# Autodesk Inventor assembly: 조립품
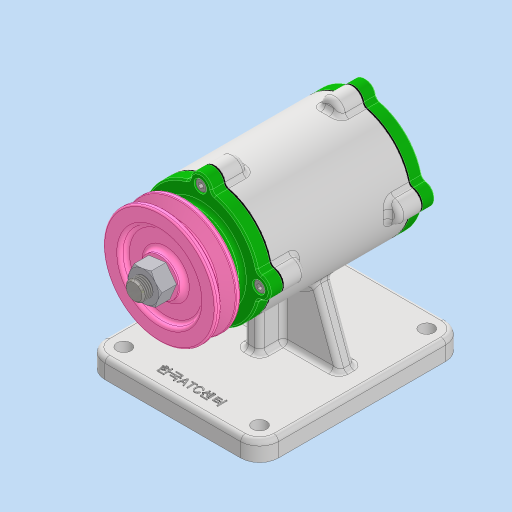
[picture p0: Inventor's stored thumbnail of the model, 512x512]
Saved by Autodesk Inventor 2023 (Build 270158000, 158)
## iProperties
Created: 2023-08
Part Number: 조립품
Document SubType Name: Assembly
Designer: asung
Author: asung
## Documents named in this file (12)
- C:\Users\asung\Desktop\730808V1012\조립품.iam
- C:\Users\asung\Desktop\730808V1012\본체.ipt
- C:\Users\asung\Desktop\730808V1012\베어링 6204.ipt
- C:\Users\asung\Desktop\730808V1012\앞커버.ipt
- C:\Users\asung\Desktop\730808V1012\뒤커버.ipt
- C:\Users\asung\Desktop\730808V1012\개스킷.ipt
- C:\Users\asung\Desktop\730808V1012\오일 실.ipt
- C:\Users\asung\Desktop\730808V1012\축.ipt
- C:\Users\asung\Desktop\730808V1012\볼트 M4 x 12.ipt
- C:\Users\asung\Desktop\730808V1012\키 4 x 4.ipt
- C:\Users\asung\Desktop\730808V1012\V-벨트풀리.ipt
- C:\Users\asung\Desktop\730808V1012\너트 M12 x 1.25.ipt
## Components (8 placed, 6 different names)
1. KS B 2023 6204 - 20 x 47 x 14:1
2. KS B 2023 6204 - 20 x 47 x 14:2
3. 개스킷:1
4. 개스킷:2
5. KS B 2804 D D - 20 32 8:1
6. KS B 1311 (I) 4 x 4 x 12:1
7. KS B 1012 클래스 1 일반 - 미터 M12x1.25:1
8. V-벨트풀리:1
